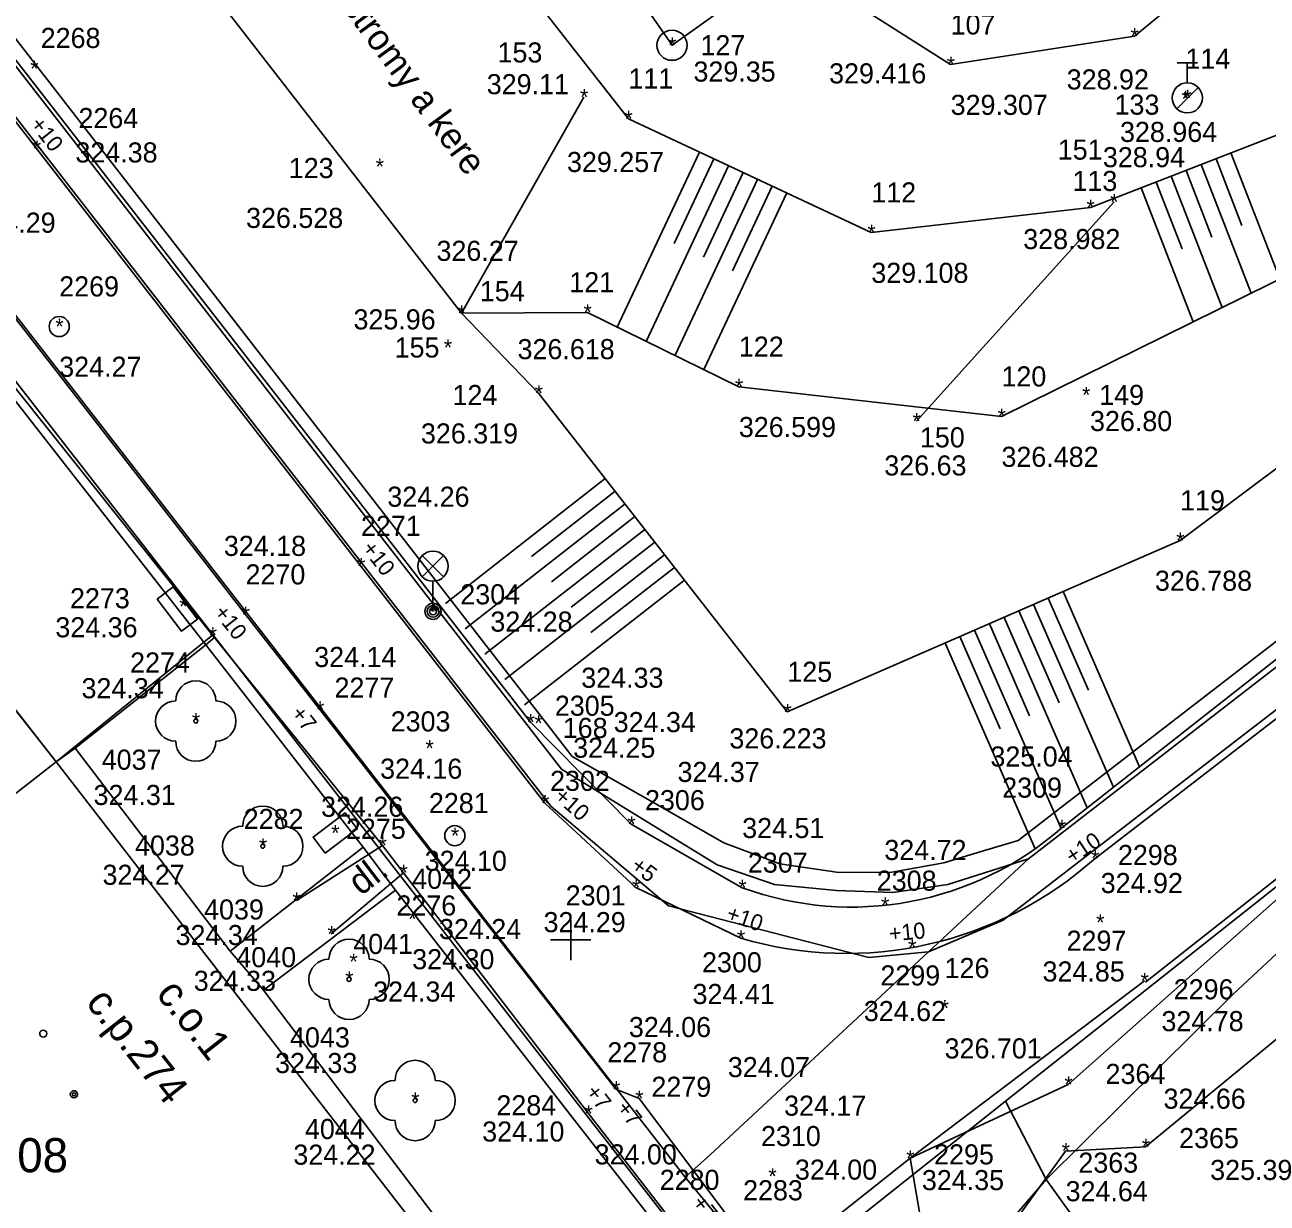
# Model space of a CAD drawing. Extents: x -600587 to -600377, y -1159886 to -1159708.
# Drawn here: x -600513.58 to -600482.67, y -1159856.55 to -1159827.23 of the extents above; entities that cross this region are included whole.
import ezdxf

# ---------------------------------------------------------------- set-up
doc = ezdxf.new("R2010")
doc.units = 0
for name, color, linetype in [('Hranice parcel', 7, 'Continuous'), ('Level 24', 7, 'Continuous'), ('Level 28', 7, 'Continuous'), ('Level 33', 7, 'Continuous'), ('Parcelní čísla', 7, 'Continuous'), ('Vnitřní kresba', 7, 'Continuous'), ('Vrstva 10', 7, 'Continuous'), ('Vrstva 11', 7, 'Continuous'), ('Vrstva 12', 7, 'Continuous'), ('Vrstva 14', 7, 'Continuous'), ('Vrstva 16', 7, 'Continuous'), ('Vrstva 20', 7, 'Continuous'), ('Vrstva 22', 7, 'Continuous'), ('Vrstva 40', 7, 'Continuous'), ('Vrstva 46', 7, 'Continuous'), ('Vrstva 58', 7, 'Continuous'), ('Vrstva 59', 7, 'Continuous'), ('Vrstva 6', 7, 'Continuous'), ('Vrstva 60', 7, 'Continuous'), ('Vrstva 63', 7, 'Continuous'), ('Vrstva 7', 7, 'Continuous'), ('Značky budov', 7, 'Continuous')]:
    doc.layers.add(name, color=color, linetype=linetype)

msp = doc.modelspace()

# ---------------------------------------------------------------- linework, layer by layer
at = {"layer": 'Hranice parcel'}
for p, q in [((-600448.05, -1159816.59), (-600488.61, -1159847.98)), ((-600489.18, -1159854.01), (-600495, -1159858.63)), ((-600488.17, -1159855.96), (-600489.18, -1159854.01))]:
    msp.add_line(p, q, dxfattribs=at)
for points in [[(-600488.61, -1159847.98), (-600490.62, -1159848.62), (-600491.99, -1159848.82), (-600493.39, -1159848.77), (-600494.93, -1159848.62), (-600496.36, -1159848.13), (-600500.23, -1159845.75), (-600572.32, -1159752.89), (-600572.98, -1159751.48), (-600573.33, -1159750.24), (-600573.44, -1159748.95), (-600573.44, -1159747.6), (-600573.32, -1159746.25), (-600573.13, -1159744.93), (-600572.66, -1159743.72), (-600571.05, -1159741.4), (-600570.22, -1159740.33), (-600564.67, -1159736.09)], [(-600508.85, -1159842.47), (-600517.35, -1159831.56), (-600519.44, -1159828.81)], [(-600465.68, -1159836.35), (-600475.51, -1159843.89), (-600483.51, -1159851.34), (-600488.17, -1159855.96)], [(-600520.064, -1159851.241), (-600512.8, -1159845.57), (-600512.33, -1159845.23), (-600509.08, -1159842.66), (-600508.85, -1159842.47)], [(-600495.86, -1159859.22), (-600495.98, -1159858.93), (-600497.49, -1159857.08), (-600508.85, -1159842.47)], [(-600488.61, -1159847.98), (-600491.1, -1159850.3), (-600496.53, -1159855.35), (-600497.15, -1159855.9), (-600496.12, -1159857.16), (-600495, -1159858.63)], [(-600489.02, -1159859.21), (-600490.1, -1159858.2), (-600488.17, -1159855.96)], [(-600484.806, -1159860.645), (-600488.17, -1159855.96)]]:
    msp.add_lwpolyline(points, dxfattribs=at)
at = {"layer": 'Level 24'}
for points in [[(-600510.289, -1159841.519), (-600509.687, -1159842.317), (-600509.288, -1159842.016), (-600509.89, -1159841.218)], [(-600506.11, -1159847.841), (-600505.311, -1159847.239), (-600505.612, -1159846.839), (-600506.411, -1159847.441)]]:
    msp.add_lwpolyline(points, close=True, dxfattribs=at)
at = {"layer": 'Level 28'}
for p, q in [((-600484.91, -1159828.175), (-600484.41, -1159828.175)), ((-600484.66, -1159828.675), (-600484.66, -1159828.175)), ((-600484.918, -1159829.322), (-600484.388, -1159828.792))]:
    msp.add_line(p, q, dxfattribs=at)
msp.add_circle((-600484.66, -1159829.05), 0.375, dxfattribs=at)
at = {"layer": 'Level 33'}
for p, q in [((-600503.692, -1159840.966), (-600503.162, -1159840.436)), ((-600503.692, -1159840.436), (-600503.162, -1159840.966)), ((-600503.427, -1159841.076), (-600503.427, -1159841.826))]:
    msp.add_line(p, q, dxfattribs=at)
for centre, radius in [((-600503.427, -1159840.701), 0.375), ((-600503.427, -1159841.826), 0.2), ((-600503.427, -1159841.826), 0.145), ((-600503.427, -1159841.826), 0.0876)]:
    msp.add_circle(centre, radius, dxfattribs=at)
at = {"layer": 'Vnitřní kresba'}
for p, q in [((-600580.267, -1159748.971), (-600497.15, -1159855.9)), ((-600499.96, -1159845.44), (-600571.89, -1159752.7)), ((-600503.93, -1159842.26), (-600567.61, -1159760.2)), ((-600448.94, -1159816.68), (-600488.87, -1159847.53)), ((-600447.51, -1159817.31), (-600489.24, -1159849.51)), ((-600489.18, -1159854.01), (-600460.61, -1159831.35)), ((-600515.92, -1159833.9), (-600509.08, -1159842.66)), ((-600519.66, -1159836.79), (-600512.8, -1159845.57)), ((-600500.49, -1159846.68), (-600503.93, -1159842.26)), ((-600505.16, -1159847.69), (-600509.08, -1159842.66)), ((-600512.33, -1159845.23), (-600508.47, -1159850.28)), ((-600512.8, -1159845.57), (-600503.89, -1159857.08)), ((-600498.07, -1159846.51), (-600499.96, -1159845.44)), ((-600496.19, -1159847.58), (-600498.07, -1159846.51)), ((-600497.57, -1159849.15), (-600500.49, -1159846.68)), ((-600508.47, -1159850.28), (-600505.16, -1159847.69)), ((-600504.36, -1159848.76), (-600505.16, -1159847.69)), ((-600494.8, -1159848.11), (-600496.19, -1159847.58)), ((-600488.87, -1159847.53), (-600489.79, -1159847.8)), ((-600490.72, -1159848.08), (-600492.01, -1159848.31)), ((-600489.79, -1159847.8), (-600490.72, -1159848.08)), ((-600493.33, -1159848.32), (-600494.8, -1159848.11)), ((-600492.01, -1159848.31), (-600493.33, -1159848.32)), ((-600504.36, -1159848.76), (-600507.64, -1159851.25)), ((-600497.73, -1159857.27), (-600504.36, -1159848.76)), ((-600492.58, -1159850.44), (-600497.57, -1159849.15)), ((-600489.24, -1159849.51), (-600491.1, -1159850.3)), ((-600508.47, -1159850.28), (-600507.64, -1159851.25)), ((-600491.1, -1159850.3), (-600492.58, -1159850.44)), ((-600507.64, -1159851.25), (-600503.34, -1159856.93))]:
    msp.add_line(p, q, dxfattribs=at)
at = {"layer": 'Vrstva 10'}
for p, q in [((-600504.681, -1159847.647), (-600504.163, -1159848.327)), ((-600499.56, -1159854.317), (-600496.968, -1159857.663))]:
    msp.add_line(p, q, dxfattribs=at)
at = {"layer": 'Vrstva 11'}
for p, q in [((-600520.248, -1159821.439), (-600513.287, -1159830.311)), ((-600505.219, -1159840.698), (-600513.287, -1159830.311)), ((-600498.85, -1159834.772), (-600496.798, -1159830.397)), ((-600482.355, -1159833.554), (-600483.574, -1159830.42)), ((-600498.126, -1159835.112), (-600496.074, -1159830.737)), ((-600497.423, -1159832.671), (-600496.436, -1159830.567)), ((-600483.075, -1159833.91), (-600484.319, -1159830.71)), ((-600483.301, -1159832.225), (-600483.946, -1159830.565)), ((-600497.402, -1159835.452), (-600495.35, -1159831.077)), ((-600496.699, -1159833.011), (-600495.712, -1159830.907)), ((-600483.795, -1159834.266), (-600485.065, -1159831)), ((-600484.047, -1159832.515), (-600484.692, -1159830.855)), ((-600495.975, -1159833.351), (-600494.988, -1159831.246)), ((-600484.515, -1159834.622), (-600485.811, -1159831.29)), ((-600484.792, -1159832.805), (-600485.438, -1159831.145)), ((-600496.678, -1159835.791), (-600494.626, -1159831.416)), ((-600515.844, -1159831.929), (-600508.09, -1159841.905)), ((-600484.84, -1159840.063), (-600476.191, -1159833.587)), ((-600502.72, -1159834.41), (-600500.798, -1159836.399)), ((-600503.117, -1159841.626), (-600499.14, -1159838.523)), ((-600500.974, -1159840.461), (-600498.894, -1159838.839)), ((-600502.625, -1159842.257), (-600498.648, -1159839.154)), ((-600500.482, -1159841.092), (-600498.402, -1159839.469)), ((-600502.133, -1159842.888), (-600498.156, -1159839.785)), ((-600499.99, -1159841.723), (-600497.91, -1159840.1)), ((-600501.641, -1159843.518), (-600497.664, -1159840.415)), ((-600499.498, -1159842.354), (-600497.418, -1159840.731)), ((-600501.149, -1159844.149), (-600497.172, -1159841.046)), ((-600487.119, -1159843.785), (-600488.119, -1159841.494)), ((-600485.851, -1159845.69), (-600487.752, -1159841.334)), ((-600508.09, -1159841.905), (-600506.24, -1159844.264)), ((-600487.852, -1159844.105), (-600488.852, -1159841.814)), ((-600486.5, -1159846.201), (-600488.485, -1159841.654)), ((-600478.865, -1159841.734), (-600486.956, -1159847.971)), ((-600488.585, -1159844.425), (-600489.585, -1159842.134)), ((-600487.15, -1159846.713), (-600489.219, -1159841.974)), ((-600489.318, -1159844.745), (-600490.318, -1159842.454)), ((-600487.8, -1159847.224), (-600489.952, -1159842.294)), ((-600488.449, -1159847.736), (-600490.685, -1159842.614)), ((-600506.24, -1159844.264), (-600498.874, -1159853.71)), ((-600476.997, -1159844.167), (-600485.703, -1159851.054)), ((-600504.681, -1159847.647), (-600506.826, -1159849.019)), ((-600504.163, -1159848.327), (-600505.956, -1159849.852)), ((-600495.769, -1159849.957), (-600498.378, -1159848.698)), ((-600485.726, -1159851.02), (-600491.557, -1159855.432)), ((-600498.874, -1159853.71), (-600498.297, -1159853.946)), ((-600498.297, -1159853.946), (-600496.159, -1159856.789)), ((-600491.557, -1159855.432), (-600495.283, -1159858.38)), ((-600491.107, -1159858.044), (-600491.557, -1159855.432)), ((-600490.033, -1159858.492), (-600487.688, -1159855.251))]:
    msp.add_line(p, q, dxfattribs=at)
for points in [[(-600502.72, -1159834.41), (-600509.56, -1159825.58), (-600519.31, -1159812.85), (-600530.48, -1159797.91), (-600554.16, -1159766.46)], [(-600472.677, -1159816.619), (-600485.977, -1159827.515), (-600490.548, -1159828.224), (-600493.772, -1159826.17), (-600497.07, -1159821.79)], [(-600502.87, -1159824.07), (-600498.564, -1159829.569), (-600492.522, -1159832.403), (-600487.072, -1159831.78), (-600481.048, -1159829.438), (-600476.419, -1159825.97)], [(-600475.267, -1159827.89), (-600480.537, -1159832.655), (-600489.284, -1159836.98), (-600495.817, -1159836.239), (-600499.585, -1159834.387), (-600502.72, -1159834.41)], [(-600500.798, -1159836.399), (-600494.611, -1159844.328), (-600484.84, -1159840.063)], [(-600505.219, -1159840.698), (-600500.643, -1159846.598), (-600498.378, -1159848.698)]]:
    msp.add_lwpolyline(points, dxfattribs=at)
for radius in [0.375, 0.0005]:
    msp.add_circle((-600497.48, -1159827.741), radius, dxfattribs=at)
msp.add_arc((-600493.145, -1159841.053), 9.283, 253.5813, 311.8176, dxfattribs=at)
at = {"layer": 'Vrstva 12'}
msp.add_lwpolyline([(-600499.17, -1159825.3), (-600497.48, -1159827.74), (-600495.08, -1159826.02), (-600496.72, -1159823.6), (-600497.65, -1159824.35)], close=True, dxfattribs=at)
at = {"layer": 'Vrstva 14'}
for p, q in [((-600502.72, -1159834.41), (-600499.67, -1159829.03)), ((-600491.4, -1159837.09), (-600486.48, -1159831.64)), ((-600487.621, -1159853.594), (-600476.997, -1159844.167)), ((-600475.361, -1159846.637), (-600485.697, -1159855.144)), ((-600487.621, -1159853.594), (-600491.557, -1159855.432)), ((-600485.697, -1159855.144), (-600487.688, -1159855.251))]:
    msp.add_line(p, q, dxfattribs=at)
at = {"layer": 'Vrstva 20'}
for points in [[(-600512.8, -1159845.57), (-600520.767, -1159835.442)], [(-600502.538, -1159860.037), (-600504.48, -1159857.53), (-600503.89, -1159857.08), (-600512.8, -1159845.57), (-600520.767, -1159851.79)]]:
    msp.add_lwpolyline(points, dxfattribs=at)
for radius in [0.09, 0.0398]:
    msp.add_circle((-600512.36, -1159853.84), radius, dxfattribs=at)
at = {"layer": 'Vrstva 22'}
for centre in [(-600509.328, -1159844.555), (-600507.661, -1159847.668), (-600505.514, -1159850.98), (-600503.871, -1159853.995)]:
    msp.add_circle(centre, 0.05, dxfattribs=at)
for centre, start, end in [((-600509.328, -1159844.055), 0, 180), ((-600509.828, -1159844.555), 90, 270), ((-600508.828, -1159844.555), 270, 90), ((-600509.328, -1159845.055), 180, 0), ((-600507.661, -1159847.168), 0, 180), ((-600508.161, -1159847.668), 90, 270), ((-600507.161, -1159847.668), 270, 90), ((-600507.661, -1159848.168), 180, 0), ((-600505.514, -1159850.48), 0, 180), ((-600506.014, -1159850.98), 90, 270), ((-600505.014, -1159850.98), 270, 90), ((-600505.514, -1159851.48), 180, 0), ((-600503.871, -1159853.495), 0, 180), ((-600504.371, -1159853.995), 90, 270), ((-600503.371, -1159853.995), 270, 90), ((-600503.871, -1159854.495), 180, 0)]:
    msp.add_arc(centre, 0.5, start, end, dxfattribs=at)
at = {"layer": 'Vrstva 6'}
for centre in [(-600512.725, -1159834.74), (-600502.883, -1159847.406)]:
    msp.add_circle(centre, 0.25, dxfattribs=at)
at = {"layer": 'Vrstva 63'}
for p, q in [((-600500, -1159849.5), (-600500, -1159850.5)), ((-600500.5, -1159850), (-600499.5, -1159850))]:
    msp.add_line(p, q, dxfattribs=at)
at = {"layer": 'Vrstva 7'}
for p, q in [((-600508.91, -1159842.42), (-600517.443, -1159831.729)), ((-600487.783, -1159847.211), (-600479.599, -1159840.769)), ((-600512.8, -1159845.57), (-600508.91, -1159842.42)), ((-600508.91, -1159842.42), (-600504.681, -1159847.647)), ((-600501, -1159844.58), (-600498.492, -1159847.123)), ((-600498.492, -1159847.123), (-600495.734, -1159848.701)), ((-600504.163, -1159848.327), (-600499.56, -1159854.317))]:
    msp.add_line(p, q, dxfattribs=at)
msp.add_lwpolyline([(-600566.21, -1159760.89), (-600549.54, -1159782.24), (-600535.27, -1159800.58), (-600519.17, -1159821.21), (-600501, -1159844.58)], dxfattribs=at)
msp.add_arc((-600493.015, -1159841.252), 7.93, 249.947, 311.281, dxfattribs=at)
at = {"layer": 'Značky budov'}
msp.add_circle((-600513.123, -1159852.33), 0.0875, dxfattribs=at)

# ---------------------------------------------------------------- texts
at = {"layer": 'Parcelní čísla'}
msp.add_text('1608', height=0.85, dxfattribs=at).set_placement((-600515.033, -1159855.78))
at = {"layer": 'Vrstva 16'}
for s, rotation, p in [('+10', 308.3679, (-600513.471, -1159829.718)), ('+10', 308.3679, (-600505.218, -1159840.269)), ('+10', 308.3679, (-600508.901, -1159841.862)), ('+7', 308.3679, (-600506.982, -1159844.375)), ('+10', 318.8408, (-600500.439, -1159846.473)), ('+10', 33.5458, (-600487.524, -1159848.128)), ('+5', 322.8296, (-600498.534, -1159848.222)), ('+10', 340.7571, (-600496.159, -1159849.498)), ('+10', 5.4352, (-600492.064, -1159850.041)), ('+7', 308.3679, (-600499.652, -1159853.796)), ('+7', 308.3679, (-600498.886, -1159854.194)), ('+7', 308.3679, (-600497.006, -1159856.552))]:
    msp.add_text(s, height=0.4, rotation=rotation, dxfattribs=at).set_placement(p)
at = {"layer": 'Vrstva 40'}
for s, rotation, p in [('stromy a kere', 306.4091, (-600505.705, -1159826.794)), ('dl.', 37.3346, (-600505.222, -1159848.917))]:
    msp.add_text(s, height=0.65, rotation=rotation, dxfattribs=at).set_placement(p)
at = {"layer": 'Vrstva 46'}
for s, p in [('c.o.1', (-600510.338, -1159851.347)), ('c.p.274', (-600512.087, -1159851.564))]:
    msp.add_text(s, height=0.75, rotation=308.2142, dxfattribs=at).set_placement(p)
at = {"layer": 'Vrstva 58'}
for s, p in [('329.35', (-600496.946, -1159828.645)), ('329.416', (-600493.572, -1159828.691)), ('329.11', (-600502.089, -1159828.959)), ('328.92', (-600487.661, -1159828.841)), ('329.307', (-600490.548, -1159829.474)), ('328.964', (-600486.335, -1159830.147)), ('324.38', (-600512.323, -1159830.658)), ('329.257', (-600500.093, -1159830.895)), ('328.94', (-600486.761, -1159830.775)), ('324.29', (-600514.859, -1159832.405)), ('326.528', (-600508.077, -1159832.286)), ('328.982', (-600488.742, -1159832.813)), ('326.27', (-600503.339, -1159833.105)), ('329.108', (-600492.522, -1159833.653)), ('325.96', (-600505.404, -1159834.81)), ('326.618', (-600501.323, -1159835.551)), ('324.27', (-600512.725, -1159835.99)), ('326.80', (-600487.081, -1159837.34)), ('326.319', (-600503.727, -1159837.649)), ('326.599', (-600495.817, -1159837.489)), ('326.482', (-600489.284, -1159838.23)), ('326.63', (-600492.199, -1159838.445)), ('324.26', (-600504.562, -1159839.222)), ('324.18', (-600508.629, -1159840.446)), ('326.788', (-600485.466, -1159841.313)), ('324.28', (-600501.999, -1159842.33)), ('324.36', (-600512.821, -1159842.471)), ('324.14', (-600506.381, -1159843.21)), ('324.33', (-600499.738, -1159843.726)), ('324.34', (-600512.17, -1159843.987)), ('324.34', (-600498.931, -1159844.83)), ('324.25', (-600499.939, -1159845.468)), ('326.223', (-600496.053, -1159845.236)), ('325.04', (-600489.559, -1159845.686)), ('324.16', (-600504.742, -1159845.989)), ('324.37', (-600497.343, -1159846.07)), ('324.31', (-600511.87, -1159846.643)), ('324.26', (-600506.21, -1159846.936)), ('324.51', (-600495.734, -1159847.465)), ('324.10', (-600503.633, -1159848.281)), ('324.72', (-600492.198, -1159848.012)), ('324.27', (-600511.648, -1159848.629)), ('324.92', (-600486.815, -1159848.834)), ('324.29', (-600500.676, -1159849.807)), ('324.34', (-600509.831, -1159850.129)), ('324.24', (-600503.277, -1159849.979)), ('324.30', (-600503.944, -1159850.729)), ('324.85', (-600488.262, -1159851.034)), ('324.33', (-600509.378, -1159851.267)), ('324.34', (-600504.915, -1159851.534)), ('324.41', (-600496.969, -1159851.595)), ('324.62', (-600492.708, -1159852.019)), ('324.78', (-600485.304, -1159852.27)), ('324.06', (-600498.553, -1159852.417)), ('326.701', (-600490.699, -1159852.948)), ('324.33', (-600507.355, -1159853.312)), ('324.07', (-600496.092, -1159853.414)), ('324.17', (-600494.692, -1159854.373)), ('324.66', (-600485.252, -1159854.199)), ('324.10', (-600502.202, -1159855.016)), ('324.22', (-600506.9, -1159855.592)), ('324.00', (-600499.405, -1159855.585)), ('324.00', (-600494.422, -1159855.964)), ('325.39', (-600484.091, -1159855.972)), ('324.35', (-600491.264, -1159856.225)), ('324.64', (-600487.688, -1159856.501))]:
    msp.add_text(s, height=0.5, dxfattribs=at).set_placement(p)
at = {"layer": 'Vrstva 59'}
for s, p in [('107', (-600490.548, -1159827.474)), ('2268', (-600513.186, -1159827.809)), ('153', (-600501.821, -1159828.17)), ('127', (-600496.772, -1159827.99)), ('114', (-600484.707, -1159828.325)), ('111', (-600498.564, -1159828.819)), ('133', (-600486.47, -1159829.468)), ('2264', (-600512.246, -1159829.802)), ('151', (-600487.883, -1159830.587)), ('123', (-600507.014, -1159831.045)), ('113', (-600487.517, -1159831.366)), ('112', (-600492.522, -1159831.653)), ('2269', (-600512.725, -1159833.99)), ('121', (-600500.035, -1159833.887)), ('154', (-600502.262, -1159834.11)), ('155', (-600504.381, -1159835.51)), ('122', (-600495.817, -1159835.489)), ('120', (-600489.284, -1159836.23)), ('124', (-600502.942, -1159836.693)), ('149', (-600486.852, -1159836.69)), ('150', (-600491.313, -1159837.746)), ('119', (-600484.84, -1159839.313)), ('2271', (-600505.219, -1159839.948)), ('2270', (-600508.09, -1159841.155)), ('2273', (-600512.457, -1159841.749)), ('2304', (-600502.747, -1159841.651)), ('2274', (-600510.962, -1159843.347)), ('125', (-600494.611, -1159843.578)), ('2277', (-600505.876, -1159843.971)), ('2305', (-600500.395, -1159844.423)), ('2303', (-600504.479, -1159844.813)), ('168', (-600500.198, -1159844.975)), ('4037', (-600511.668, -1159845.765)), ('2302', (-600500.514, -1159846.292)), ('2309', (-600489.265, -1159846.461)), ('2281', (-600503.528, -1159846.844)), ('2306', (-600498.152, -1159846.772)), ('2282', (-600508.135, -1159847.239)), ('2275', (-600505.592, -1159847.485)), ('4038', (-600510.839, -1159847.901)), ('2298', (-600486.386, -1159848.136)), ('2307', (-600495.593, -1159848.326)), ('4042', (-600503.944, -1159848.729)), ('2308', (-600492.385, -1159848.775)), ('2301', (-600500.125, -1159849.142)), ('4039', (-600509.121, -1159849.492)), ('2276', (-600504.336, -1159849.392)), ('4041', (-600505.41, -1159850.35)), ('2297', (-600487.664, -1159850.269)), ('4040', (-600508.319, -1159850.679)), ('2300', (-600496.733, -1159850.806)), ('126', (-600490.699, -1159850.948)), ('2299', (-600492.296, -1159851.133)), ('2296', (-600484.999, -1159851.478)), ('4043', (-600506.983, -1159852.674)), ('2278', (-600499.089, -1159853.045)), ('2364', (-600486.695, -1159853.583)), ('2279', (-600497.992, -1159853.903)), ('2284', (-600501.849, -1159854.364)), ('4044', (-600506.612, -1159854.954)), ('2310', (-600495.266, -1159855.129)), ('2365', (-600484.864, -1159855.18)), ('2295', (-600490.959, -1159855.585)), ('2363', (-600487.371, -1159855.791)), ('2280', (-600497.786, -1159856.218)), ('2283', (-600495.712, -1159856.478))]:
    msp.add_text(s, height=0.5, dxfattribs=at).set_placement(p)
at = {"layer": 'Vrstva 60'}
for p in [(-600486.075, -1159827.715), (-600497.578, -1159827.94), (-600513.448, -1159828.524), (-600490.646, -1159828.424), (-600499.768, -1159829.23), (-600484.805, -1159829.275), (-600484.758, -1159829.25), (-600498.662, -1159829.769), (-600513.385, -1159830.511), (-600504.854, -1159830.96), (-600487.17, -1159831.98), (-600486.578, -1159831.84), (-600492.62, -1159832.603), (-600502.818, -1159834.61), (-600499.683, -1159834.587), (-600512.823, -1159834.94), (-600503.158, -1159835.46), (-600500.896, -1159836.599), (-600495.915, -1159836.439), (-600487.278, -1159836.64), (-600491.498, -1159837.29), (-600489.382, -1159837.18), (-600484.938, -1159840.263), (-600505.317, -1159840.898), (-600509.741, -1159841.902), (-600508.188, -1159842.105), (-600503.525, -1159842.026), (-600509.008, -1159842.62), (-600506.338, -1159844.464), (-600509.426, -1159844.755), (-600494.709, -1159844.528), (-600501.098, -1159844.78), (-600500.903, -1159844.81), (-600503.615, -1159845.429), (-600500.741, -1159846.798), (-600505.959, -1159847.54), (-600498.59, -1159847.323), (-600487.881, -1159847.411), (-600507.759, -1159847.868), (-600504.779, -1159847.847), (-600502.981, -1159847.606), (-600487.054, -1159848.171), (-600504.261, -1159848.527), (-600498.476, -1159848.898), (-600495.832, -1159848.901), (-600506.924, -1159849.219), (-600492.281, -1159849.338), (-600504.042, -1159849.679), (-600486.929, -1159849.765), (-600506.054, -1159850.052), (-600495.867, -1159850.157), (-600491.606, -1159850.39), (-600505.508, -1159850.74), (-600505.612, -1159851.18), (-600485.824, -1159851.22), (-600490.797, -1159851.898), (-600498.972, -1159853.91), (-600487.719, -1159853.794), (-600503.969, -1159854.195), (-600498.395, -1159854.146), (-600499.658, -1159854.517), (-600487.786, -1159855.451), (-600485.795, -1159855.344), (-600491.655, -1159855.632), (-600495.083, -1159856.079)]:
    msp.add_text('*', height=0.4, dxfattribs=at).set_placement(p)

doc.saveas('drawing.dxf')
